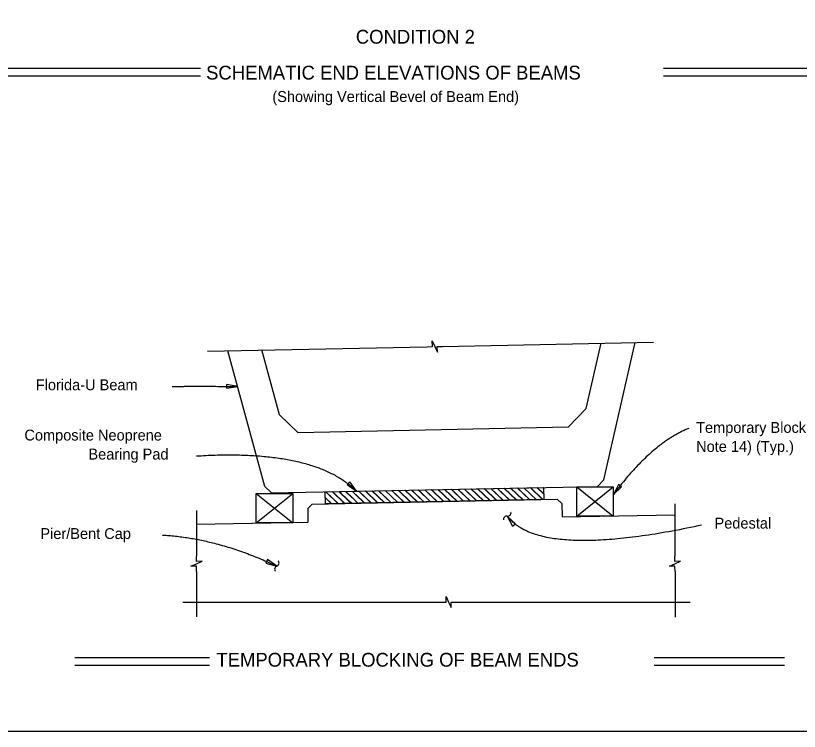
# Model space of a CAD drawing. Extents: x 120784.3 to 120844.8, y 120560 to 120604.3.
# Drawn here: x 120800.18 to 120811.07, y 120583.39 to 120593.34 of the extents above; entities that cross this region are included whole.
import ezdxf

# ---------------------------------------------------------------- set-up
doc = ezdxf.new("R2010")
doc.units = 0
for name, color, linetype in [('ActivePts-ConstElements', 7, 'Continuous'), ('AdhocPoint_dp', 7, 'Continuous'), ('Border', 7, 'Continuous'), ('Patterning', 7, 'Continuous'), ('PlotBorder_dp', 7, 'Continuous'), ('SheetBorder_dp', 7, 'Continuous'), ('TextMisc', 7, 'Continuous')]:
    doc.layers.add(name, color=color, linetype=linetype)

msp = doc.modelspace()

# ---------------------------------------------------------------- linework, layer by layer
at = {"layer": 'ActivePts-ConstElements'}
msp.add_lwpolyline([(120790.703, 120583.387), (120821.491, 120583.387), (120821.491, 120602.846), (120790.703, 120602.846)], close=True, dxfattribs=at)
at = {"layer": 'AdhocPoint_dp'}
for p, q in [((120808.351, 120586.883), (120808.788, 120588.793)), ((120803.641, 120586.789), (120803.128, 120588.679)), ((120808.264, 120586.793), (120808.351, 120586.883)), ((120803.731, 120586.703), (120803.641, 120586.789)), ((120803.731, 120586.703), (120808.264, 120586.793)), ((120804.297, 120586.547), (120807.705, 120586.615)), ((120807.705, 120586.615), (120807.769, 120586.554)), ((120804.236, 120586.483), (120804.297, 120586.547)), ((120807.769, 120586.554), (120807.773, 120586.367)), ((120804.236, 120586.483), (120804.239, 120586.296)), ((120807.773, 120586.367), (120809.336, 120586.398)), ((120802.689, 120586.265), (120804.239, 120586.296))]:
    msp.add_line(p, q, dxfattribs=at)
at = {"layer": 'Border'}
for p, q in [((120807.974, 120586.784), (120808.483, 120586.378)), ((120807.974, 120586.378), (120808.483, 120586.784)), ((120803.521, 120586.695), (120804.029, 120586.288)), ((120803.521, 120586.288), (120804.029, 120586.695))]:
    msp.add_line(p, q, dxfattribs=at)
for points in [[(120807.974, 120586.784), (120808.483, 120586.784), (120808.483, 120586.378), (120807.974, 120586.378)], [(120803.521, 120586.695), (120804.029, 120586.695), (120804.029, 120586.288), (120803.521, 120586.288)]]:
    msp.add_lwpolyline(points, close=True, dxfattribs=at)
at = {"layer": 'Patterning'}
for p, q in [((120804.81, 120586.586), (120804.669, 120586.721)), ((120804.812, 120586.588), (120804.673, 120586.721)), ((120804.855, 120586.633), (120804.761, 120586.723)), ((120804.857, 120586.635), (120804.765, 120586.723)), ((120804.9, 120586.68), (120804.853, 120586.725)), ((120804.902, 120586.681), (120804.856, 120586.725)), ((120804.945, 120586.726), (120804.945, 120586.727)), ((120805.115, 120586.564), (120804.947, 120586.725)), ((120805.118, 120586.564), (120804.949, 120586.726)), ((120805.206, 120586.565), (120805.036, 120586.729)), ((120805.21, 120586.565), (120805.04, 120586.729)), ((120805.298, 120586.567), (120805.128, 120586.731)), ((120805.302, 120586.567), (120805.132, 120586.731)), ((120805.39, 120586.569), (120805.22, 120586.732)), ((120805.393, 120586.569), (120805.223, 120586.732)), ((120805.482, 120586.571), (120805.312, 120586.734)), ((120805.485, 120586.571), (120805.315, 120586.734)), ((120805.573, 120586.573), (120805.404, 120586.736)), ((120805.577, 120586.573), (120805.407, 120586.736)), ((120805.665, 120586.575), (120805.495, 120586.738)), ((120805.669, 120586.575), (120805.499, 120586.738)), ((120805.757, 120586.576), (120805.587, 120586.74)), ((120805.76, 120586.576), (120805.59, 120586.74)), ((120805.849, 120586.578), (120805.679, 120586.742)), ((120805.852, 120586.578), (120805.682, 120586.742)), ((120805.941, 120586.58), (120805.771, 120586.743)), ((120805.944, 120586.58), (120805.774, 120586.743)), ((120806.032, 120586.582), (120805.862, 120586.745)), ((120806.036, 120586.582), (120805.866, 120586.745)), ((120806.124, 120586.584), (120805.954, 120586.747)), ((120806.127, 120586.584), (120805.957, 120586.747)), ((120806.216, 120586.586), (120806.046, 120586.749)), ((120806.219, 120586.586), (120806.049, 120586.749)), ((120806.308, 120586.587), (120806.138, 120586.751)), ((120806.311, 120586.588), (120806.141, 120586.751)), ((120806.399, 120586.589), (120806.229, 120586.753)), ((120806.403, 120586.589), (120806.233, 120586.753)), ((120806.491, 120586.591), (120806.321, 120586.754)), ((120806.494, 120586.591), (120806.324, 120586.754)), ((120806.583, 120586.593), (120806.413, 120586.756)), ((120806.586, 120586.593), (120806.416, 120586.756)), ((120806.675, 120586.595), (120806.505, 120586.758)), ((120806.678, 120586.595), (120806.508, 120586.758)), ((120806.766, 120586.597), (120806.596, 120586.76)), ((120806.77, 120586.597), (120806.6, 120586.76)), ((120806.858, 120586.598), (120806.688, 120586.762)), ((120806.861, 120586.599), (120806.692, 120586.762)), ((120806.95, 120586.6), (120806.78, 120586.764)), ((120806.953, 120586.6), (120806.783, 120586.764)), ((120807.042, 120586.602), (120806.872, 120586.765)), ((120807.045, 120586.602), (120806.875, 120586.765)), ((120807.133, 120586.604), (120806.963, 120586.767)), ((120807.137, 120586.604), (120806.967, 120586.767)), ((120807.225, 120586.606), (120807.055, 120586.769)), ((120807.229, 120586.606), (120807.059, 120586.769)), ((120807.317, 120586.608), (120807.147, 120586.771)), ((120807.32, 120586.608), (120807.15, 120586.771)), ((120807.409, 120586.609), (120807.239, 120586.773)), ((120807.412, 120586.61), (120807.242, 120586.773)), ((120807.5, 120586.611), (120807.33, 120586.775)), ((120807.504, 120586.611), (120807.334, 120586.775)), ((120807.516, 120586.686), (120807.422, 120586.776)), ((120807.516, 120586.69), (120807.426, 120586.777)), ((120807.515, 120586.765), (120807.501, 120586.778)), ((120807.515, 120586.768), (120807.504, 120586.778)), ((120807.514, 120586.778), (120807.514, 120586.778)), ((120804.568, 120586.553), (120804.483, 120586.634)), ((120804.564, 120586.553), (120804.483, 120586.631)), ((120804.656, 120586.554), (120804.486, 120586.718)), ((120804.659, 120586.554), (120804.489, 120586.718)), ((120804.748, 120586.556), (120804.578, 120586.72)), ((120804.751, 120586.556), (120804.581, 120586.72)), ((120804.931, 120586.56), (120804.857, 120586.631)), ((120804.935, 120586.56), (120804.859, 120586.633)), ((120805.023, 120586.562), (120804.902, 120586.678)), ((120805.026, 120586.562), (120804.904, 120586.68)), ((120804.839, 120586.558), (120804.812, 120586.584)), ((120804.843, 120586.558), (120804.814, 120586.586))]:
    msp.add_line(p, q, dxfattribs=at)
msp.add_lwpolyline([(120804.481, 120586.718), (120807.514, 120586.778), (120807.518, 120586.612), (120804.484, 120586.551)], close=True, dxfattribs=at)
at = {"layer": 'PlotBorder_dp'}
for p, q in [((120802.747, 120592.603), (120795.497, 120592.603)), ((120802.747, 120592.603), (120795.497, 120592.603)), ((120817.278, 120592.603), (120809.179, 120592.603)), ((120817.278, 120592.603), (120809.179, 120592.603)), ((120802.747, 120592.495), (120795.497, 120592.495)), ((120802.747, 120592.495), (120795.497, 120592.495)), ((120817.278, 120592.495), (120809.179, 120592.495)), ((120817.278, 120592.495), (120809.179, 120592.495)), ((120806.109, 120588.739), (120809.042, 120588.798)), ((120802.844, 120588.674), (120805.897, 120588.735)), ((120809.337, 120586.552), (120809.337, 120585.822)), ((120802.689, 120586.455), (120802.689, 120585.822)), ((120802.689, 120585.61), (120802.689, 120584.98)), ((120809.341, 120585.61), (120809.341, 120584.972)), ((120802.502, 120585.184), (120806.088, 120585.184)), ((120806.3, 120585.184), (120809.549, 120585.184)), ((120802.87, 120584.411), (120801.002, 120584.411)), ((120810.86, 120584.411), (120809.053, 120584.411)), ((120802.87, 120584.303), (120801.002, 120584.303)), ((120810.86, 120584.303), (120809.053, 120584.303))]:
    msp.add_line(p, q, dxfattribs=at)
for points in [[(120805.897, 120588.735), (120805.969, 120588.736), (120805.968, 120588.814), (120806.003, 120588.737), (120806.039, 120588.66), (120806.037, 120588.738), (120806.109, 120588.739)], [(120802.693, 120585.61), (120802.692, 120585.682), (120802.614, 120585.681), (120802.691, 120585.716), (120802.768, 120585.751), (120802.69, 120585.75), (120802.689, 120585.822)], [(120809.341, 120585.61), (120809.34, 120585.682), (120809.262, 120585.681), (120809.339, 120585.716), (120809.416, 120585.751), (120809.338, 120585.75), (120809.337, 120585.822)], [(120806.088, 120585.185), (120806.16, 120585.185), (120806.16, 120585.262), (120806.194, 120585.185), (120806.228, 120585.107), (120806.228, 120585.185), (120806.3, 120585.185)]]:
    msp.add_lwpolyline(points, dxfattribs=at)
for points in [[(120803.264, 120588.179), (120803.108, 120588.209), (120803.107, 120588.156)], [(120804.916, 120586.726), (120804.823, 120586.855), (120804.786, 120586.818)], [(120808.484, 120586.678), (120808.598, 120586.788), (120808.555, 120586.82)], [(120807.01, 120586.38), (120807.081, 120586.238), (120807.124, 120586.27)], [(120803.807, 120585.683), (120803.677, 120585.774), (120803.654, 120585.727)]]:
    msp.add_lwpolyline(points, close=True, dxfattribs=at)
for centre, start, end in [((120807.017, 120586.424), 260.5328, 12.26), ((120807.002, 120586.335), 80.5328, 192.26), ((120803.793, 120585.726), 288.7395, 40.4667), ((120803.821, 120585.642), 108.7395, 220.4667)]:
    msp.add_arc(centre, 0.0447, start, end, dxfattribs=at)
for points in [[(120802.354, 120588.182), (120802.858, 120588.188), (120803.264, 120588.179)], [(120809.531, 120587.599), (120809.006, 120587.384), (120808.484, 120586.678)], [(120802.69, 120587.216), (120804.319, 120587.318), (120804.916, 120586.726)], [(120809.709, 120586.253), (120807.46, 120585.768), (120807.01, 120586.38)], [(120802.219, 120586.116), (120802.991, 120586.071), (120803.807, 120585.683)]]:
    msp.add_open_spline(points, degree=2, dxfattribs=at)
at = {"layer": 'TextMisc'}
for p, q in [((120803.845, 120587.788), (120803.6, 120588.689)), ((120808.107, 120587.874), (120808.315, 120588.783)), ((120808.107, 120587.874), (120807.862, 120587.619)), ((120803.845, 120587.788), (120804.1, 120587.543)), ((120804.1, 120587.543), (120807.862, 120587.619))]:
    msp.add_line(p, q, dxfattribs=at)

# ---------------------------------------------------------------- texts
at = {"layer": 'PlotBorder_dp'}
for s, p in [('Temporary Blocking (See ', (120809.634, 120587.536)), ('Composite Neoprene', (120800.299, 120587.43)), ('Note 14) (Typ.)', (120809.634, 120587.272)), ('Bearing Pad', (120801.189, 120587.166))]:
    msp.add_text(s, height=0.1512, dxfattribs=at).set_placement(p)
at = {"layer": 'SheetBorder_dp'}
for s, height, p in [('CONDITION 2', 0.192, (120804.905, 120592.948)), ('SCHEMATIC END ELEVATIONS OF BEAMS', 0.192, (120802.824, 120592.449)), ('(Showing Vertical Bevel of Beam End)', 0.1512, (120803.745, 120592.137)), ('Florida-U Beam', 0.1512, (120800.457, 120588.129)), ('Pedestal', 0.1512, (120809.89, 120586.206)), ('Pier/Bent Cap', 0.1512, (120800.521, 120586.061)), ('TEMPORARY BLOCKING OF BEAM ENDS', 0.192, (120802.967, 120584.286))]:
    msp.add_text(s, height=height, dxfattribs=at).set_placement(p)

doc.saveas('drawing.dxf')
